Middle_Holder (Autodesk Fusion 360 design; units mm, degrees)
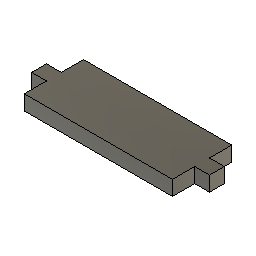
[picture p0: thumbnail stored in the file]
parameter "Length_Z" = 15
parameter "Length_X_Long" = 150
parameter "HLXL" = 75 (= "Length_X_Long / 2")
parameter "Pin_Length_Y" = 15 (= "Length_Z")
parameter "Length_Y_Total" = 60 (= "Pin_Length_Y + 45 mm")
parameter "HLYT" = 30 (= "Length_Y_Total / 2")
sketch "Sketch1" plane through (0, 0, 0) normal (0, 0, 1) x axis (1, 0, 0)
  line L1 (75, 30) -> (-75, 30)
  line L2 (-75, -30) -> (75, -30)
  line L3 (90, 7.5) -> (75, 7.5)
  line L4 (90, -7.5) -> (90, 7.5)
  line L5 (75, -7.5) -> (90, -7.5)
  line L6 (-90, 7.5) -> (-75, 7.5)
  line L7 (-90, -7.5) -> (-90, 7.5)
  line L8 (-75, -7.5) -> (-90, -7.5)
  line L9 (-75, -7.5) -> (-75, -30)
  line L10 (-75, 30) -> (-75, 7.5)
  line L11 (75, 7.5) -> (75, 30)
  line L12 (75, -30) -> (75, -7.5)
  point P10 (-75, 7.5)
  point P11 (-90, 7.5)
  point P6 (75, 7.5)
  point P7 (90, 7.5)
  point P2 (-75, 30)
  point P3 (75, 30)
  point P1 (0, 0)
  point P12 (-90, -7.5)
  point P4 (75, -30)
  horizontal L1
  vertical L11
  horizontal L2
  vertical L9
  horizontal L3
  vertical L4
  horizontal L5
  horizontal L6
  vertical L7
  horizontal L8
  coincident P10 L9
  collinear L9 L10
  collinear L11 L12
  equal L9 L10
  equal L11 L12
  equal L9 L12
  dimension "d2" distance P10 P11 = 15 (= "Length_Z")
  dimension "d3" distance P6 P7 = 15 (= "Length_Z")
  dimension "d7" distance P2 P3 = 150 (= "Length_X_Long")
  dimension "d9" distance P1 P3 = 75 (= "HLXL")
  dimension "d11" distance P11 P12 = 15 (= "Length_Z")
  dimension "d13" distance P3 P4 = 60 (= "Length_Y_Total")
  dimension "d15" distance P1 L1 = 30 (= "HLYT")
extrude "Extrude1" new body sketch "Sketch1" profile of L1 L12 L2 L10 L3 L4 L5 L6 L7 L8 along normal blind 15 (= "Length_Z")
